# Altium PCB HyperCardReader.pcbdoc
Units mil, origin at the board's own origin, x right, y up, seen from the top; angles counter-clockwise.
Board outline 2181.35 x 1859.05 mil, 2 copper layers (Top Layer, Bottom Layer); 44 components, 43 nets, 186 pads, 101 vias.
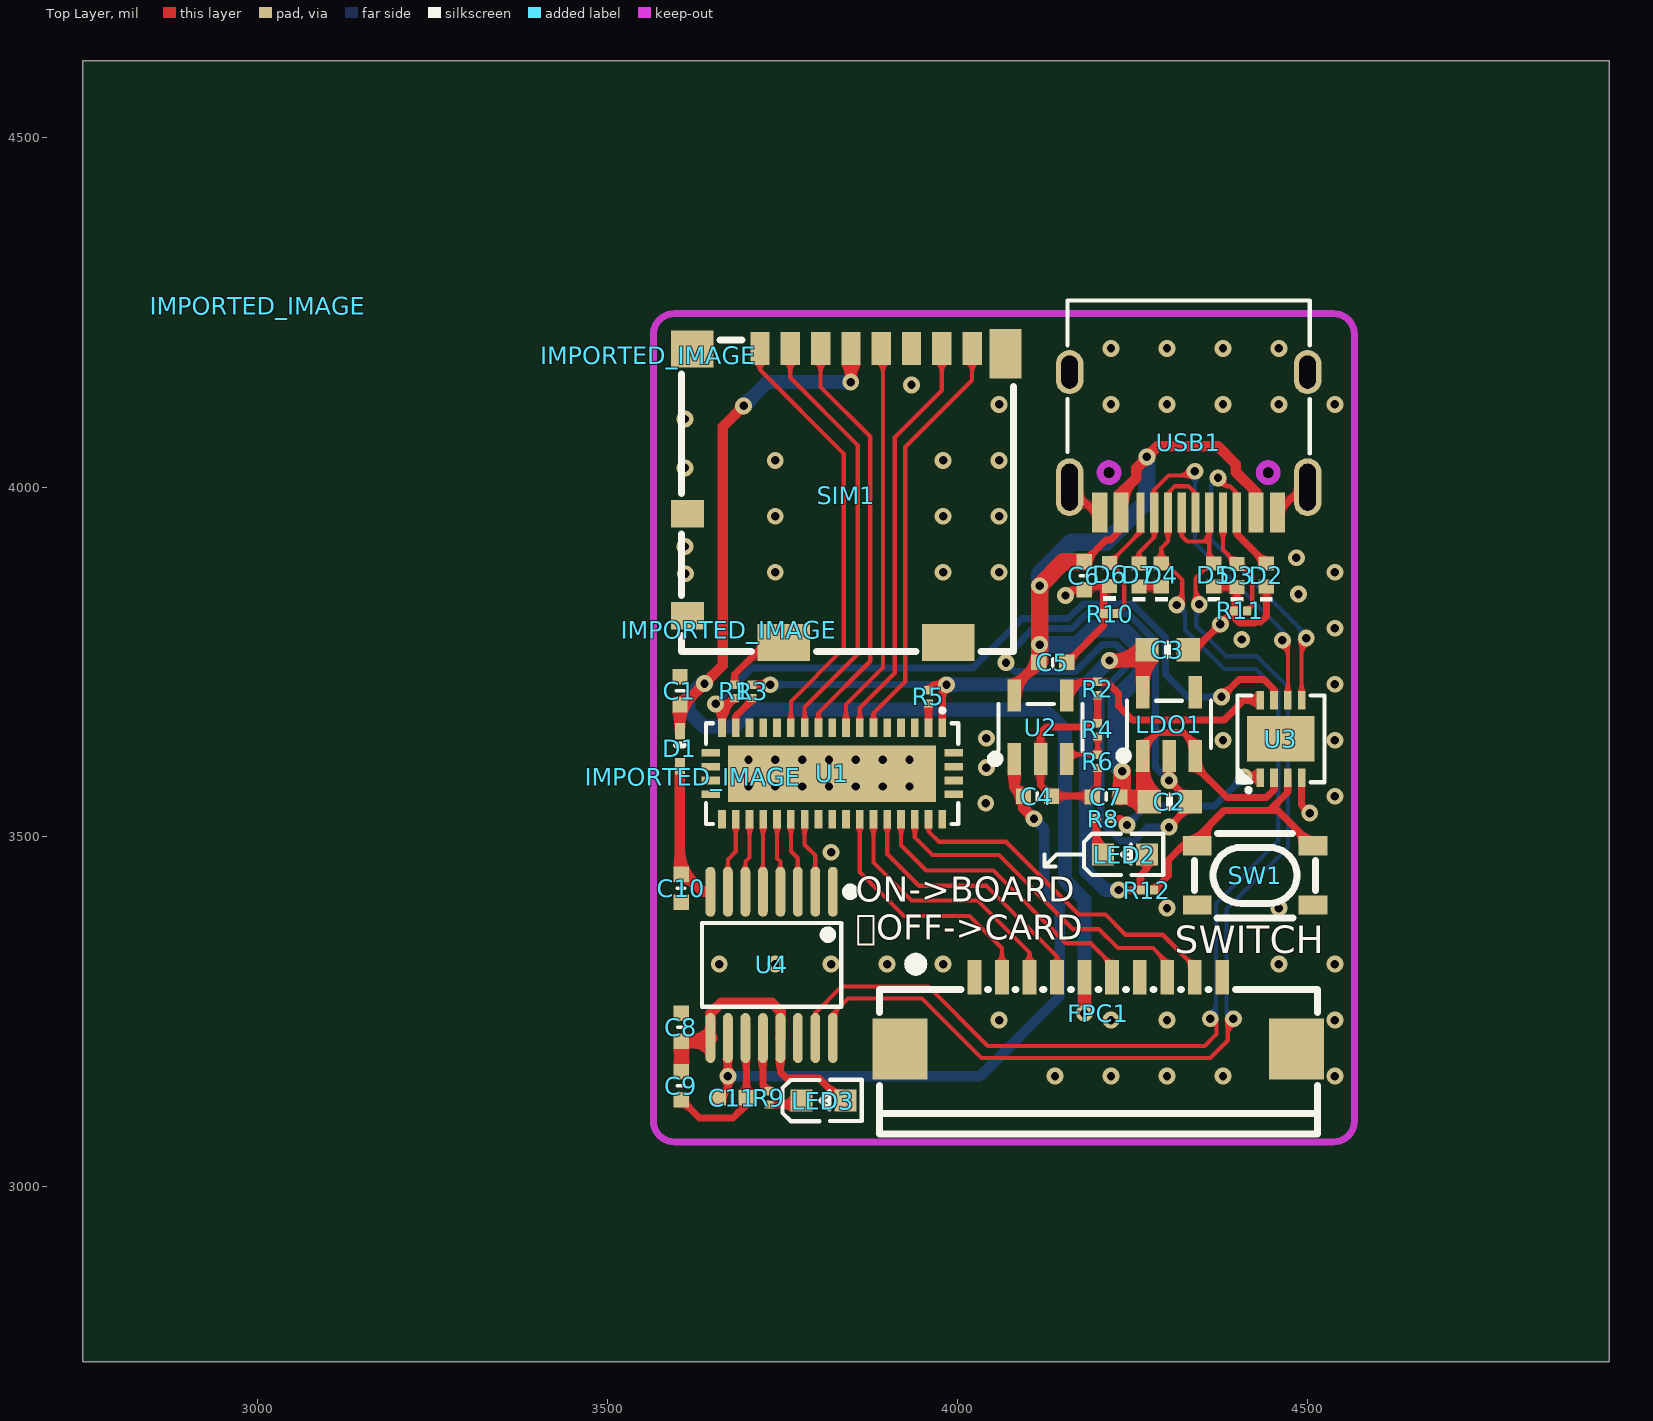
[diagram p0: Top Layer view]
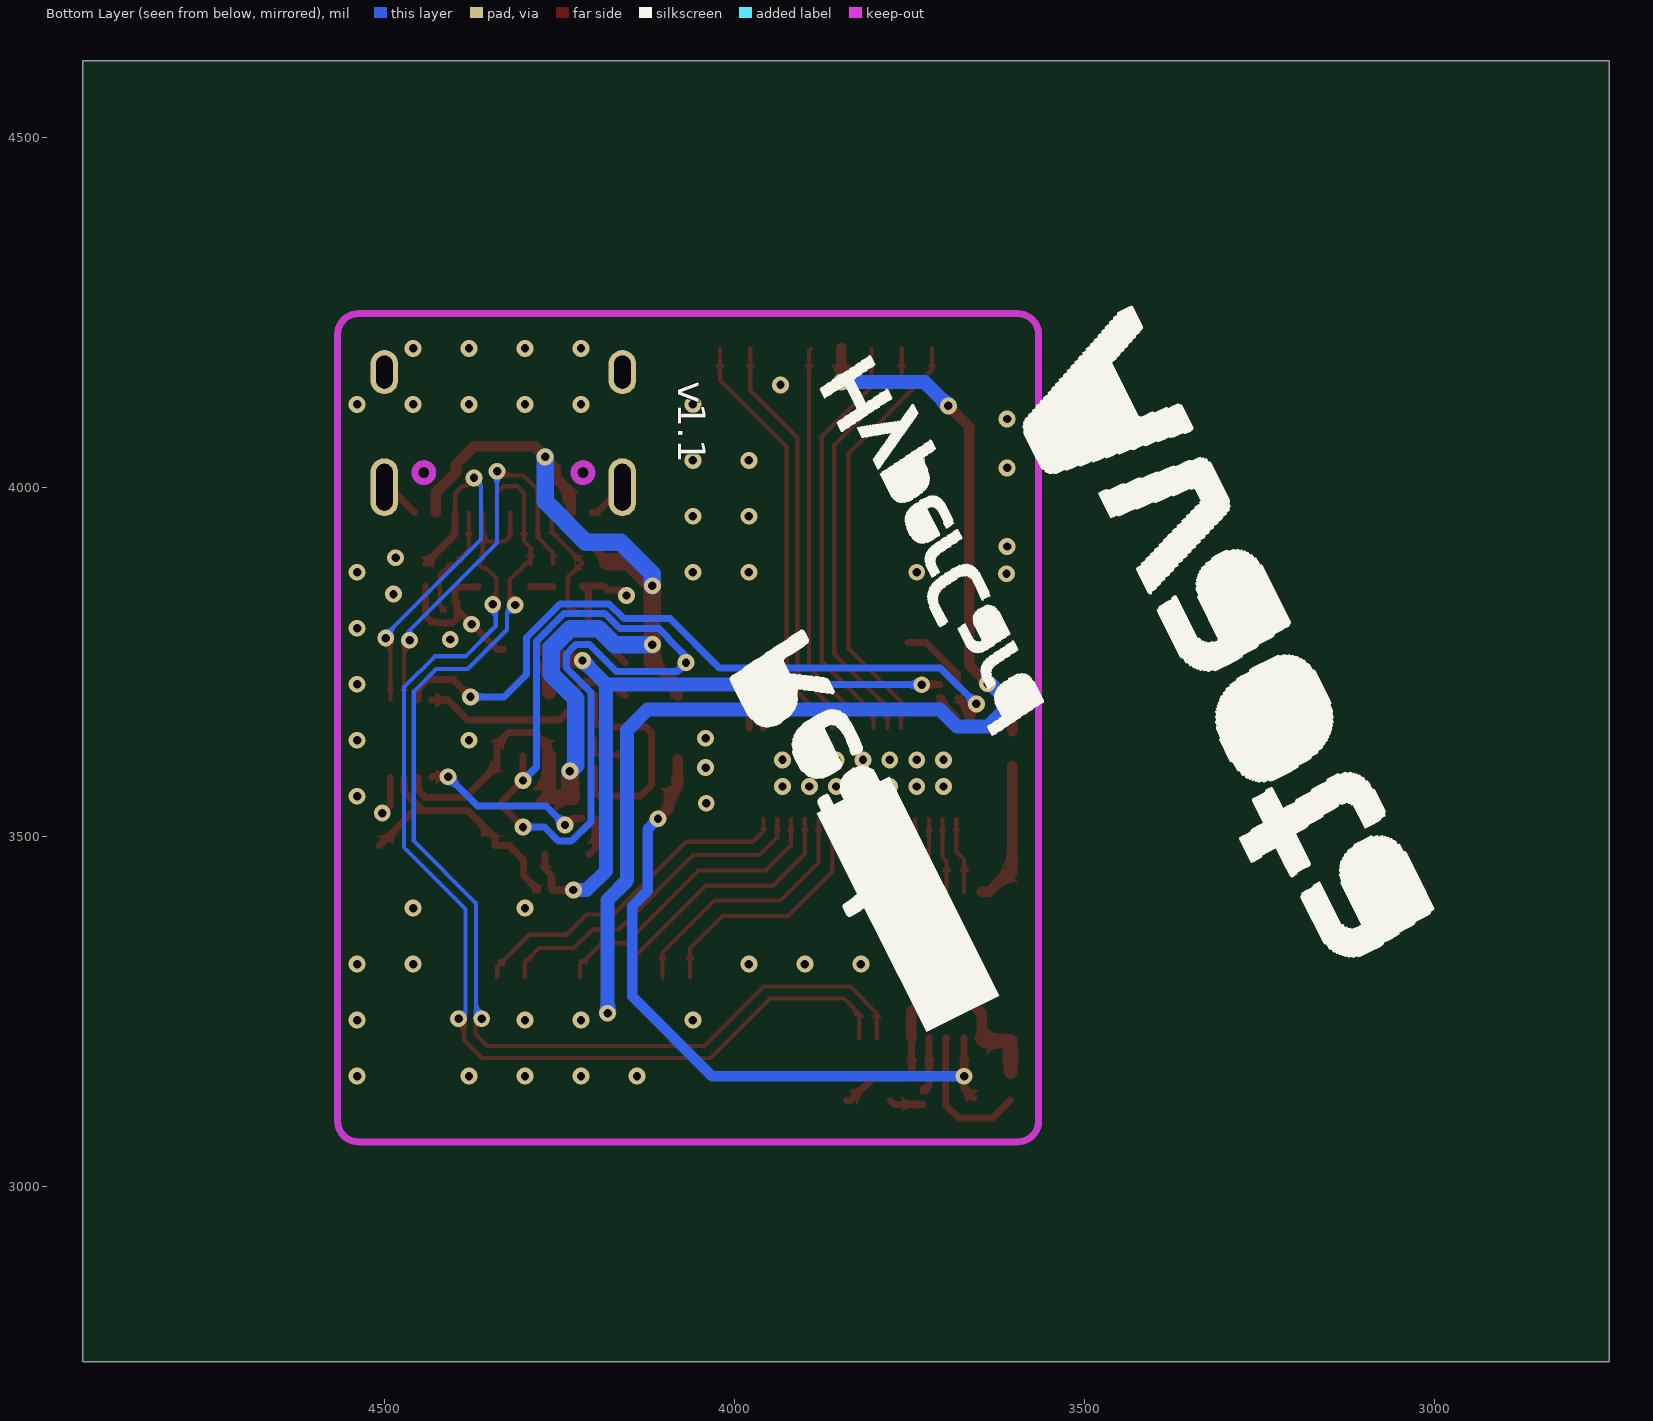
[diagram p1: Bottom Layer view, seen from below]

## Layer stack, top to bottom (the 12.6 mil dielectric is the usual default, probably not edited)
Top Layer: signal copper (thickness not stored)
Dielectric: dielectric 12.6, FR-4, Dk 4.8
Bottom Layer: signal copper (thickness not stored)

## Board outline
4931.35,2750 2750,2750 2750,4609.05 4931.35,4609.05

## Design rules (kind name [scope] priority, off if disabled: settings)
Clearance copperThickness1oz [All] p1: gap=7 ignorepadtopadclearanceinfootprint=FALSE except(4: Track-Track; 6: Track-SMDPad SMDPad-SMDPad Track-THPad SMDPad-THPad THPad-THPad Track-Via SMDPad-Via THPad-Via Via-Via Track-Fill SMDPad-Fill THPad-Fill Via-Fill Fill-Fill SMDPad-Region THPad-Region Via-Region Fill-Region Region-Region Track-Poly SMDPad-Poly THPad-Poly Via-Poly Fill-Poly Poly-Poly Track-Text SMDPad-Text THPad-Text Via-Text Fill-Text Region-Text Poly-Text Text-Text; 6.9: Track-Hole SMDPad-Hole THPad-Hole Via-Hole Fill-Hole Region-Hole Poly-Hole Text-Hole Sheet-Hole; 11.8: Track-Region Region-Poly Track-Sheet SMDPad-Sheet THPad-Sheet Via-Sheet Fill-Sheet Region-Sheet Poly-Sheet Text-Sheet)
Clearance copperThickness2oz [All] p1: gap=7 ignorepadtopadclearanceinfootprint=FALSE except(6: Track-SMDPad SMDPad-SMDPad Track-THPad SMDPad-THPad THPad-THPad Track-Via SMDPad-Via THPad-Via Via-Via Track-Fill SMDPad-Fill THPad-Fill Via-Fill Fill-Fill SMDPad-Region THPad-Region Via-Region Fill-Region Region-Region Track-Poly SMDPad-Poly THPad-Poly Via-Poly Fill-Poly Poly-Poly Track-Text SMDPad-Text THPad-Text Via-Text Fill-Text Region-Text Poly-Text Text-Text; 6.9: Track-Hole SMDPad-Hole THPad-Hole Via-Hole Fill-Hole Region-Hole Poly-Hole Text-Hole Sheet-Hole; 8: Track-Track; 11.8: Track-Region Region-Poly Track-Sheet SMDPad-Sheet THPad-Sheet Via-Sheet Fill-Sheet Region-Sheet Poly-Sheet Text-Sheet)
DiffPairsRouting differentialPair [All] p1: maxuncoupledlength=10 minlimit=0 maxlimit=5.9843 mostfreqgap=5.9843 toplayer_minwidth=5 toplayer_prefwidth=10 toplayer_maxwidth=100 bottomlayer_minwidth=5 bottomlayer_prefwidth=10 bottomlayer_maxwidth=100
PasteMaskExpansion pasteMaskExpansion [All] p1: expansion=0
PlaneConnect innerPlane [All] p1: planeconnectstyle=Relief reliefexpansion=20 reliefentries=4 reliefconductorwidth=10 reliefairgap=10
PolygonConnect copperRegion [All] p1: connectstyle=Relief reliefentries=4 reliefconductorwidth=10 polygonreliefangle="90 Angle" airgapwidth=10
RoutingVias viaSize [All] p1: viastyle="Through Hole" holewidth=12.0078 minholewidth=11.811 maxholewidth=248.0314 width=24.0158 minwidth=19.685 maxwidth=393.7008
SolderMaskExpansion solderMaskExpansion [All] p1: useseparateexpansions=TRUE expansion=2.0079 expansionbottom=2.0079
Width copperThickness1oz [All] p1: maxlimit=100 minlimit=5 preferedwidth=10
Width copperThickness2oz [All] p1: maxlimit=100 minlimit=8 preferedwidth=10

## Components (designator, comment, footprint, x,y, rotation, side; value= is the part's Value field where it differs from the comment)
C1 "CAP_0402" c0402-nsk 3603.35,3709 r270 top
C2 "CAP_0603" C0603-NSK 4303.35,3550 r180 top
C3 "CAP_0603" C0603-NSK 4300.35,3767.54 r180 top
C4 "CAP_0402" c0402-nsk 4114.36,3558.28 r180 top
C5 "CAP_0402" c0402-nsk 4136.36,3749.28 r180 top
C6 "CAP_0402" c0402-nsk 4181.35,3873 r90 top
C7 "CAP_0402" c0402-nsk 4212.35,3557 r0 top
C8 "CAP_0402" c0402-nsk 3605.35,3228 r270 top
C9 "CAP_0402" c0402-nsk 3605.35,3144 r90 top
C10 "CAP_0402" c0402-nsk 3605.25,3426.67 r90 top
C11 "CAP_0402" c0402-nsk 3678.35,3127 r180 top
D1 "B5819WT_C2997265" "SOD-523_L1.2-W0.8-LS1.6-RD-1 NSK" 3603.35,3626 r270 top
D2 "0402ESDA-05N" d0402 4441.35,3874 r90 top
D3 "0402ESDA-05N" d0402 4399.44,3873.72 r90 top
D4 "0402ESDA-05N" d0402 4291.35,3874 r90 top
D5 "0402ESDA-05N" d0402 4366.35,3874 r90 top
D6 "0402ESDA-05N" d0402 4217.35,3875 r90 top
D7 "0402ESDA-05N" d0402 4259.35,3874 r90 top
FPC1 "AFA01-S10FCC-00" FPC-SMD_AFA01-S10FCC-00 4201.35,3248 r0 top
IMPORTED_IMAGE "IMPORTED_IMAGE" IMPORTED_IMAGE 3000,4258.92 r0 top
IMPORTED_IMAGE "IMPORTED_IMAGE" IMPORTED_IMAGE 3557.69,4188.12 r0 top
IMPORTED_IMAGE "IMPORTED_IMAGE" IMPORTED_IMAGE 3621.76,3586.01 r0 top
IMPORTED_IMAGE "IMPORTED_IMAGE" IMPORTED_IMAGE 3672.82,3796.23 r0 top
LDO1 "ME6211C33M5G-N" SOT-23-5_L3.0-W1.7-P0.95-LS2.8-BL 4302.35,3661 r0 top
LED2 "LED_0603-R" LED_0603 4241.35,3475 r0 top
LED3 "LED_0603-R" LED_0603 3810.47,3123.31 r0 top
R1 "Res_0201" "r0201 nsk" 3681.35,3708 r90 top
R2 "Res_0201" "r0201 nsk" 4200.35,3712 r90 top
R3 "Res_0201" "r0201 nsk" 3706.35,3708 r90 top
R4 "Res_0201" "r0201 nsk" 4200.35,3653 r90 top
R5 "Res_0201" "r0201 nsk" 3958.35,3700 r90 top
R6 "Res_0201" "r0201 nsk" 4200.35,3608 r90 top
R8 "Res_0201" "r0201 nsk" 4208.35,3526 r0 top
R9 "Res_0201" "r0201 nsk" 3730.35,3127 r90 top
R10 "Res_0201" "r0201 nsk" 4218.35,3819 r0 top
R11 "Res_0201" "r0201 nsk" 4404.35,3823 r0 top
R12 "Res_0201" "r0201 nsk" 4271.35,3424 r0 top
SIM1 "1040310811" SIM-SMD_8P-1040310811 3841.35,3988 r180 top
SW1 "SKRPACE010" KEY-SMD_4P-L4.2-W3.2-P2.20-LS4.6 4425.35,3445 r0 top
U1 "TS3DV642A0RUAR" WFQFN-42_L9.0-W3.5-P0.50-BL-EP 3821.04,3590.48 r180 top
U2 "SY6280AAC_C55136" SOT-23-5_L3.0-W1.7-P0.95-LS2.8-BL 4118.77,3656.53 r0 top
U3 "STC8G1K08-36I-DFN8" DFN-8_L3.0-W3.0-P0.50-BL-EP 4462.35,3640 r0 top
U4 "GL823K-HCY04" SSOP-16_L4.9-W3.9-P0.64-LS6.0-BL 3734.35,3317 r180 top
USB1 "TYPEC-304-BCP16" USB-C-SMD_TYPEC-304-BCP16-1 4330.35,4064 r180 top

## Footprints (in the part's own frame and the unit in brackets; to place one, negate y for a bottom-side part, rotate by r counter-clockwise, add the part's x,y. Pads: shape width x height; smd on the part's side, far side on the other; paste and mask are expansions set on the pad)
c0402-nsk [mil]
  rect 22x22 smd: 1(-19.99,0) 2(20.01,0)
  silkscreen extent 0,-5 0,6
C0603-NSK [mm]
  rect 0.85x0.85 smd: 1(-0.75,0) 2(0.75,0)
  silkscreen extent 0,-0.21 0,0.21
d0402 [mil]
  rect 19.89x21.68 smd: 1(-16.4,0) 2(16.4,0)
  silkscreen extent -37,-9 -31,9
DFN-8_L3.0-W3.0-P0.50-BL-EP [mm]
  rect 0.28x0.665 smd: 1(-0.75,-1.407) 2(-0.25,-1.407) 3(0.25,-1.407) 4(0.75,-1.407) 5(0.75,1.407) 6(0.25,1.407) 7(-0.25,1.407) 8(-0.75,1.407)
  rect 2.45x1.65 smd: 9(0,0)
  silkscreen extent -1.58,-1.93 1.58,1.58
FPC-SMD_AFA01-S10FCC-00 [mm]
  rect 0.5x1.25 smd: 1(-4.5,1.3) 2(-3.5,1.3) 3(-2.501,1.3) 4(-1.5,1.3) 5(-0.501,1.3) 6(0.499,1.3) 7(1.5,1.3) 8(2.499,1.3) 9(3.5,1.3) 10(4.499,1.3)
  rect 2x2.2 smd: 11(-7.2,-1.3) 12(7.2,-1.3)
  silkscreen extent -7.94,-4.39 7.95,0.86
IMPORTED_IMAGE [mil]
KEY-SMD_4P-L4.2-W3.2-P2.20-LS4.6 [mm]
  rect 1.05x0.7 smd: 1(-2.1,1.075) 2(2.1,1.075) 3(-2.1,-1.075) 4(2.1,-1.075)
  silkscreen extent -2.2,-1.55 2.2,1.52
LED_0603 [mil]
  rect 31.5x31.5 smd: 1(-33.5,-0.4) 2(29.5,-0.2)
  silkscreen extent -61,-30 53,30
"r0201 nsk" [mil]
  rect 11.93x12.76 smd: 1(-9.51,0) 2(9.51,0)
SIM-SMD_8P-1040310811 [mm]
  rect 0.7x1.2 smd: 1(3.138,-5.337) 2(2.037,-5.337) 3(0.938,-5.337) 4(-0.162,-5.337) 5(-1.263,-5.337) 6(-2.363,-5.337) 7(-3.462,-5.337) 8(-4.562,-5.337)
  rect 1.17x1.8 smd: 9(-5.773,-5.138)
  rect 1.55x1.35 smd: 10(5.598,-5.313)
  rect 1.2x1 smd: 11(5.773,0.663) 12(5.773,4.363)
  rect 1.9x1.35 smd: 13(2.273,5.337) 14(-3.697,5.337)
  silkscreen extent -6.07,-5.64 5.99,5.67
"SOD-523_L1.2-W0.8-LS1.6-RD-1 NSK" [mm]
  rect 0.6x0.36 smd: 1(-0.635,0) 2(0.635,0)
  silkscreen extent -0.13,-0.13 -0.13,0.13
SOT-23-5_L3.0-W1.7-P0.95-LS2.8-BL [mm]
  rect 0.49x1.157 smd: 1(-0.95,-1.154) 2(0,-1.154) 3(0.95,-1.154)
  rect 0.49x1.175 smd: 4(0.95,1.154) 5(-0.95,1.154)
  silkscreen extent -1.8,-1.29 1.53,0.85
SSOP-16_L4.9-W3.9-P0.64-LS6.0-BL [mil]
  oval 14x71.45 smd: 1(-87.5,-104.52) 2(-62.5,-104.52) 3(-37.5,-104.52) 4(-12.5,-104.52) 5(12.5,-104.52) 6(37.5,-104.52) 7(62.5,-104.52) 8(87.5,-104.52) 9(87.5,104.52) 10(62.5,104.52) 11(37.5,104.52) 12(12.5,104.52) 13(-12.5,104.52) 14(-37.5,104.52) 15(-62.5,104.52) 16(-87.5,104.52)
  silkscreen extent -118,-110 100,60
USB-C-SMD_TYPEC-304-BCP16-1 [mm]
  oval 1x2.1 hole 0.6 slot 1.7 at 90 deg: 12(-4.32,1.633) 13(4.32,1.633)
  oval 1x1.6 hole 0.6 slot 1.2 at 90 deg: 14(-4.32,-2.547) 15(4.32,-2.547)
  rect 0.55x1.45 smd: A1B12(-3.225,2.547) A4B9(-2.45,2.547) B1A12(3.225,2.547) B4A9(2.45,2.547)
  rect 0.3x1.45 smd: A5(-1.25,2.547) A6(-0.25,2.547) A7(0.25,2.547) A8(1.25,2.547) B5(1.75,2.547) B6(0.75,2.547) B7(-0.75,2.547) B8(-1.75,2.547)
  Multi-Layer board cut-out: -3.215,1.102 -3.169,0.943 -3.051,0.826 -2.89,0.784 -2.729,0.826 -2.611,0.943 -2.565,1.102 -2.565,1.102 -2.611,1.262 -2.729,1.379 -2.89,1.421 -3.051,1.379 -3.169,1.262 -3.215,1.102
  Multi-Layer board cut-out: 2.565,1.102 2.611,0.943 2.729,0.826 2.89,0.784 3.051,0.826 3.169,0.943 3.215,1.102 3.215,1.102 3.169,1.262 3.051,1.379 2.89,1.421 2.729,1.379 2.611,1.262 2.565,1.102
  Multi-Layer keep-out circle w0.254: c-2.89,1.102 r0.325
  Multi-Layer keep-out circle w0.254: c2.89,1.102 r0.325
  silkscreen extent -4.4,-5.15 4.4,0.41
WFQFN-42_L9.0-W3.5-P0.50-BL-EP [mm]
  rect 0.28x0.665 smd: 1(-3.998,-1.658) 2(-3.498,-1.658) 3(-2.998,-1.658) 4(-2.498,-1.658) 5(-1.998,-1.658) 6(-1.498,-1.658) 7(-0.998,-1.658) 8(-0.498,-1.658) 9(0.002,-1.658) 10(0.502,-1.658) 11(1.002,-1.658) 12(1.502,-1.658) 13(2.002,-1.658) 14(2.502,-1.658) 15(3.002,-1.658) 16(3.502,-1.658) 17(4.002,-1.658) 22(4.002,1.658) 23(3.502,1.658) 24(3.002,1.658) 25(2.502,1.658) 26(2.002,1.658) 27(1.502,1.658) 28(1.002,1.658) 29(0.502,1.658) 30(0.002,1.658) 31(-0.498,1.658) 32(-0.998,1.658) 33(-1.498,1.658) 34(-1.998,1.658) 35(-2.498,1.658) 36(-2.998,1.658) 37(-3.498,1.658) 38(-3.998,1.658)
  rect 0.665x0.28 smd: 18(4.41,-0.75) 19(4.41,-0.25) 20(4.41,0.25) 21(4.41,0.75) 39(-4.405,0.75) 40(-4.405,0.25) 41(-4.405,-0.25) 42(-4.405,-0.75)
  rect 7.55x2.05 smd: 43(0.002,0)
  silkscreen extent -4.57,-2.36 4.58,1.83

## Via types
v1: diameter 24.02, hole 12.01, Top Layer to Bottom Layer, 101 vias

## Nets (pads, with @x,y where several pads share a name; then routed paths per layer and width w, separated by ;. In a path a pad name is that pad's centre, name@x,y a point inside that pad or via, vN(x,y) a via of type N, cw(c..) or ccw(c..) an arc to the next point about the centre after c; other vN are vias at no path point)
$1N1961: R4.1 R6.2 U2.3 | length 72.8
  Top Layer w6: U2.3 4162.57,3617.51 R6.2 R4.1
$1N4375: LED3.1 R9.1 | length 48.9
  Top Layer w10: R9.1 3771.55,3117.49 LED3.1
$1N4433: LED2.1 R8.1 | length 55.1
  Top Layer w10: R8.1 4198.84,3483.61 LED2.1
CC1: D3.2 R11.2 USB1.A5 | length 164.9
  Top Layer w6: USB1.A5 4379.56,3910.01 4380.24,3909.33 4380.91,3909.33 4386.18,3904.07 4386.18,3903.39 D3.2 4405.23,3890.12 4421.35,3874 4421.35,3830.49 R11.2
CC2: D6.2 R10.2 USB1.B5 | length 176.4
  Top Layer w6: R10.2 4238.35,3829.49 4238.35,3871.09 4231.91,3877.53 4231.22,3877.53 D6.2 4261.45,3935.5 USB1.B5
CPUX-RX: D2.2 U3.5 USB1.B8 | length 534.9
  Top Layer w6: v1(4372.35,4013) 4384.12,4001.23 4389.19,4001.23 4399.25,3991.17 USB1.B8 ; U3.5 4491.88,3777.53 v1(4498.35,3784)
  Top Layer w10: USB1.B8 4399.25,3932.5 D2.2
  Bottom Layer w6: v1(4372.35,4013) 4372.35,4012 4362.35,4002 4362.35,3925 4498.35,3789 v1(4498.35,3784)
CPUX-TX: D7.2 U3.6 USB1.A8 | length 565.8
  Top Layer w6: D7.2 4259.35,3906 4281.14,3927.79 USB1.A8 4281.14,3995.79 4301.84,4016.49 4333.38,4016.49 v1(4339.38,4022.49) ; v1(4464.35,3781) 4472.19,3773.16 U3.6
  Bottom Layer w6: v1(4339.38,4022.49) 4339.35,3920.14 4464.35,3795.14 v1(4464.35,3781)
EN: R5.1 U1.2 | length 34.9
  Top Layer w10: R5.1 3958.74,3690.1 U1.2
GND: C1.1 C2.1 C3.1 C4.1 C5.1 C6.1 C7.1 C8.1 C9.1 C10.1 C11.1 D2.1 D3.1 D4.1 D5.1 D6.1 D7.1 FPC1.1 FPC1.7 FPC1.11 FPC1.12 LDO1.2 R1.2 R2.1 R4.2 R6.1 R10.1 R11.1 SIM1.6 SIM1.9 SIM1.10 SIM1.12 SIM1.13 SIM1.14 SW1.3 SW1.4 U1.43 U2.2 U3.4 U3.9 U4.1 U4.11 U4.14 USB1.12 USB1.13 USB1.14 USB1.15 USB1.A1B12 USB1.B1A12 | length 2477
  Top Layer w10: C9.1 3631.36,3098 3679.35,3098 3698.35,3116.99 C11.1 3698.35,3210.99 U4.11 ; R1.2 3681.35,3732 3727.22,3777.86 SIM1.13 ; v1(4154.35,3845.01) 4162.35,3853.01 C6.1 4186.95,3858.6 D6.1 4208.84,3850.09 R10.1 4208.84,3801.77 C5.1 ; USB1.13 4196.29,3963.7 USB1.B1A12 ; R6.1 4200.35,3564.99 C7.1 4191.07,3558.28 C4.1 4118.77,3573.87 U2.2 4118.77,3649.42 4126.35,3657 4185.98,3657 4189.42,3660.44 4198.28,3660.44 R4.2 R2.1 ; D7.1 D4.1 ; v1(4302.35,3514) 4332.88,3544.53 C2.1 v1(4302.35,3580.53) LDO1.2 ; C3.1 4339.38,3767.54 v1(4375.83,3803.99) R11.1 ; D5.1 4366.63,3857.32 D3.1 4399.44,3836.46 4396.91,3833.93 4396.91,3825.07 R11.1 ; D2.1 4441.35,3815 4433.35,3807 4425.74,3807 4424.38,3805.64 4403.34,3805.64 4396.91,3812.07 4396.91,3820.93 R11.1 ; USB1.A1B12 4493.34,3999.72 USB1.12 ; U3.4 4491.88,3545.47 v1(4503.35,3534)
  Bottom Layer w10: v1(4302.35,3514) 4271.87,3514 4251.87,3494.01 4232.83,3494.01 4205.28,3521.56 4205.28,3706.41 4240.34,3741.48 4240.34,3761.52 4226.87,3774.99 4207.34,3774.99 4168.88,3736.53 4081.82,3736.53 v1(4069.35,3749) 4069.35,3758 4094.36,3783.01 4094.36,3784.31 4107.83,3797.78 4163.71,3797.78 4184.95,3819.02 4243.7,3819.02 4283.37,3779.35 4283.37,3599.5 v1(4302.35,3580.53)
  other v1: 4139.45,3158.1 4219.45,3158.1 4299.45,3158.1 4379.45,3158.1 4539.45,3158.1 4059.45,3238.1 4219.45,3238.1 4299.45,3238.1 4539.45,3238.1 3659.45,3318.1 3739.45,3318.1 3819.45,3318.1 3899.45,3318.1 3979.45,3318.1 4459.45,3318.1 4539.45,3318.1 4299.45,3398.1 4459.45,3398.1 3819.45,3478.1 4040.35,3548 4539.45,3558.1 3701.31,3572 3739.66,3572 3778.01,3572 3816.35,3572 3854.7,3572 3893.04,3572 3931.39,3572 4041.35,3598.98 3701.35,3610 3739.7,3610 3778.04,3610 3816.39,3610 3854.73,3610 3893.08,3610 3931.42,3610 4379.45,3638.1 4539.45,3638.1 4041.35,3641 4539.45,3718.1 4406.35,3782 4539.45,3798.1 4487.35,3847 3611.35,3876 3739.45,3878.1 3979.45,3878.1 4059.45,3878.1 4539.45,3878.1 4484.35,3899 3610.35,3915 3739.45,3958.1 3979.45,3958.1 4059.45,3958.1 3610.35,4027.33 3739.45,4038.1 3979.45,4038.1 4059.45,4038.1 3610.35,4097.22 4059.45,4118.1 4219.45,4118.1 4299.45,4118.1 4379.45,4118.1 4459.45,4118.1 4539.45,4118.1 3934.35,4146 4219.45,4198.1 4299.45,4198.1 4379.45,4198.1 4459.45,4198.1
LED-READ: R9.2 U4.12 | length 79.5
  Top Layer w10: U4.12 3721.85,3145.01 R9.2
READ-VCC-EN: R2.2 U2.4 U3.8 | length 329.6
  Top Layer w10: U2.4 4175.73,3721.51 R2.2 4213.84,3721.51 4230.35,3705 4230.35,3687 4250.35,3667 4381.35,3667 4409.76,3695.41 U3.8
SDC-CARD-CLK: SIM1.5 U1.8 | length 565.2
  Top Layer w6: U1.8 3840.63,3689.28 3893.35,3742 3893.35,4195.84 SIM1.5
SDC-CARD-CMD: SIM1.3 U1.10 | length 602.5
  Top Layer w6: U1.10 3801.26,3676.91 3875.35,3751 3875.35,4072 3804.44,4142.91 SIM1.3
SDC-CARD-D0: SIM1.7 U1.7 | length 591
  Top Layer w6: U1.7 3860.31,3683.96 3910.35,3734 3910.35,4071 3977.67,4138.31 SIM1.7
SDC-CARD-D1: SIM1.8 U1.6 | length 600.8
  Top Layer w6: U1.6 3880,3676.65 3925.35,3722 3925.35,4057 4020.98,4152.62 SIM1.8
SDC-CARD-D2: SIM1.1 U1.12 | length 623.2
  Top Layer w6: SIM1.1 3717.83,4167.52 3837.35,4048 3837.35,3769 3761.89,3693.54 U1.12
SDC-CARD-D3: SIM1.2 U1.11 | length 613.6
  Top Layer w6: SIM1.2 3761.14,4156.22 3857.35,4060 3857.35,3761 3781.57,3685.22 U1.11
SDC-CARD-DET: SIM1.11
SDC-READ-CLK: U1.26 U4.4 | length 105.6
  Top Layer w6: U1.26 3742.2,3469.15 3746.85,3464.5 U4.4
SDC-READ-CMD: U1.25 U4.5 | length 104
  Top Layer w6: U4.5 3721.85,3524.56 U1.25
SDC-READ-D0: U1.27 U4.3 | length 107.8
  Top Layer w6: U1.27 3761.89,3479.46 3771.85,3469.5 U4.3
SDC-READ-D1: U1.28 U4.2 | length 110
  Top Layer w6: U1.28 3781.57,3488.78 3796.85,3473.5 U4.2
SDC-READ-D2: U1.23 U4.7 | length 108.4
  Top Layer w6: U4.7 3671.85,3467.5 3683.15,3478.8 U1.23
SDC-READ-D3: U1.24 U4.6 | length 106.2
  Top Layer w6: U4.6 3696.85,3464.5 3702.83,3470.48 U1.24
SDC-TF-CLK: FPC1.6 U1.35 | length 427.7
  Top Layer w6: U1.35 3919.37,3487.98 3955.35,3452 4051.35,3452 4155.35,3348 4190.35,3348 4221,3317.36 FPC1.6
SDC-TF-CMD: FPC1.4 U1.34 | length 382.8
  Top Layer w6: U1.34 3899.68,3475.67 3945.35,3430 4041.35,3430 4142.3,3329.05 FPC1.4
SDC-TF-D0: FPC1.8 U1.36 | length 482.1
  Top Layer w6: U1.36 3939.05,3499.3 3964.35,3474 4059.35,3474 4165.35,3368 4202.35,3368 4229.35,3341 4279.35,3341 4299.75,3320.61 FPC1.8
SDC-TF-D1: FPC1.9 U1.37 | length 493.2
  Top Layer w6: U1.37 3958.74,3507.61 3973.35,3493 4069.35,3493 4173.35,3389 4211.35,3389 4240.35,3360 4293.35,3360 4339.15,3314.2 FPC1.9
SDC-TF-D2: FPC1.2 U1.32 | length 365.3
  Top Layer w6: U1.32 3860.31,3450.04 3923.35,3387 4017.35,3387 4063.55,3340.8 FPC1.2
SDC-TF-D3: FPC1.3 U1.33 | length 373.4
  Top Layer w6: U1.33 3880,3463.35 3934.35,3409 4028.35,3409 4102.9,3334.45 FPC1.3
SDC-TF-DET: FPC1.10
SEL: R1.1 U1.17 U3.7 | length 1038.7
  Top Layer w10: v1(3654.35,3690) 3654.35,3689.71 3663.46,3680.6 ; U1.17 3663.46,3680.6 ; R1.1 3663.46,3680.6 ; v1(4377.35,3700) 4402.35,3725 4438.35,3725 4452.51,3710.84 U3.7
  Bottom Layer w10: v1(3654.35,3690) 3705.35,3741 4021.35,3741 4092.15,3811.8 4157.9,3811.8 4179.14,3833.04 4249.5,3833.04 4297.39,3785.15 4297.39,3731.96 4329.35,3700 v1(4377.35,3700)
SEL1: R3.1 U1.16 | length 54
  Top Layer w10: U1.16 3683.15,3672.8 3691.89,3681.54 3692.28,3681.54 3698.71,3687.97 3698.71,3688.36 3707.35,3697 R3.1@3707.35,3699.49
SEL1-LED: R8.2 U3.1 | length 247.9
  Top Layer w10: R8.2 4233.35,3526 v1(4242.35,3517) ; v1(4409.35,3586) 4431.41,3586 U3.1
  Bottom Layer w10: v1(4242.35,3517) 4269.35,3544 4367.35,3544 v1(4409.35,3586)
SEL-BTN: R12.2 SW1.1 SW1.2 U3.3 | length 372.9
  Top Layer w10: R12.2 4301.35,3444.49 4301.35,3467 4321.67,3487.32 SW1.1 4342.67,3499.32 4381.35,3538 4446.35,3538 ; U3.3 4472.19,3563.84 4446.35,3538 ; SW1.2 4457.35,3538 4446.35,3538
USB0-DM: D5.2 U4.16 USB1.A7 USB1.B7 | length 1632.7
  Top Layer w6: U4.16 3821.85,3247.5 3843.35,3269 3949.35,3269 4034.35,3184 4361.35,3184 4386.35,3209 4386.35,3232 v1(4394.35,3240) ; USB1.A7 4320.51,3929.84 4328.35,3922 4352.22,3922 4359.88,3929.66 ; v1(4345.53,3832.18) 4340.35,3837.37 4340.35,3869.62 4355.13,3884.4 4360.35,3884.4 D5.2 4359.88,3896.87 4359.88,3929.66 ; USB1.B7 4359.88,3929.66
  Bottom Layer w6: v1(4345.53,3832.18) 4341.35,3828 4341.35,3801 4384.35,3758 4428.35,3758 4472.35,3714 4472.35,3485 4384.35,3397 4384.35,3250 v1(4394.35,3240)
USB0-DP: D4.2 U4.15 USB1.A6 USB1.B6 | length 1672.6
  Top Layer w6: U4.15 3796.85,3248.5 3834.35,3286 3958.35,3286 4043.35,3201 4353.35,3201 4370.35,3218 4370.35,3231 v1(4361.35,3240) ; v1(4313.36,3831.38) 4321.35,3839.37 4321.35,3867 4294.65,3893.7 D4.2 4291.35,3913 4300.82,3922.47 USB1.B6 4300.82,3991.17 4310.88,4001.23 4330.14,4001.23 4340.19,3991.18 USB1.A6
  Bottom Layer w6: v1(4313.36,3831.38) 4313.97,3831.38 4325.35,3820 4325.35,3796 4381.35,3740 4426.35,3740 4458.35,3708 4458.35,3494 4369.35,3405 4369.35,3248 v1(4361.35,3240)
VBUS-USB: C2.2 C5.2 C6.2 C7.2 LDO1.1 LDO1.3 U2.5 U3.2 USB1.A4B9 USB1.B4A9 | length 1731.8
  Top Layer w10: C6.2 4212.52,3924.18 4218.76,3924.18 4233.89,3939.31 USB1.B4A9 ; LDO1.1 4264.95,3628.6 4285.69,3649.34 4323.01,3649.34 4339.75,3632.6 LDO1.3 4339.75,3601.6 4385.35,3556 4441.35,3556 4452.51,3567.16 U3.2
  Top Layer w15: U2.5 4081.37,3714.3 C5.2 ; USB1.B4A9 4233.89,3991.54 4255.86,4013.51 4255.86,4026.56 4270.71,4041.41 v1(4270.71,4043) 4285.71,4058 4372.35,4058 4397.84,4032.51 4397.84,4021.48 4426.81,3992.51 USB1.A4B9
  Top Layer w20: C7.2 C2.2@4266.82,3557 ; LDO1.1 4264.95,3558.87 C2.2@4266.82,3557 ; C2.2 C2.2@4266.82,3557
  Top Layer w25: C5.2 4117.36,3750.28 v1(4117.36,3774.79) v1(4117.36,3859.01) 4151.36,3893.01 C6.2 ; C7.2 4235.35,3559.99 v1(4235.35,3594)
  Bottom Layer w25: v1(4117.36,3774.79) 4171.14,3774.79 4193.86,3797.51 4234.79,3797.51 4261.86,3770.44 4261.86,3732.56 4226.79,3697.5 4226.79,3602.56 v1(4235.35,3594) ; v1(4117.36,3859.01) 4117.36,3876.01 4162.35,3921 4212.35,3921 4270.71,3979.36 v1(4270.71,4043)
VCC-3V3-CARD: C10.2 D1.2 U4.8 | length 212.1
  Top Layer w15: D1.2 C10.2@3603.35,3454 ; C10.2 3603.35,3448.58 C10.2@3603.35,3454 ; U4.8 3635.83,3421.52 C10.2@3603.35,3454
VCC-3V3-LDO: C3.2 LDO1.5 LED2.2 R3.2 R5.2 R12.1 U1.1 | length 1144.9
  Top Layer w10: R3.2 v1(3732.35,3717.51) ; R5.2 3966.35,3717.51 v1(3984.35,3717.51) 3978.42,3711.58 U1.1 ; v1(4230.35,3424) R12.1 4261.35,3424.49 4261.35,3445 4270.85,3454.5 LED2.2
  Top Layer w20: v1(4217.35,3752) 4255.29,3752 C3.2@4264.95,3761.66 ; LDO1.5 C3.2@4264.95,3761.66 ; C3.2 C3.2@4264.95,3761.66
  Bottom Layer w10: v1(3732.35,3717.51) v1(3984.35,3717.51)
  Bottom Layer w20: v1(3984.35,3717.51) 4183.86,3717.51 ; v1(4217.35,3752) 4183.86,3718.51 4183.86,3717.51 ; v1(4230.35,3424) 4211.35,3424 4183.86,3451.49 4183.86,3717.51
VCC-CARD: C1.2 D1.1 FPC1.5 SIM1.4 | length 1808.9
  Top Layer w15: D1.1 C1.2 3608.35,3688.99 v1(3638.38,3719.02) 3664.35,3745 3664.35,4086 v1(3694.35,4116) ; v1(3847.35,4150) 3847.75,4150.4 SIM1.4
  Top Layer w18: v1(4181.35,3248) 4181.65,3248.3 FPC1.5
  Bottom Layer w20: v1(3638.38,3719.02) 3634.38,3719.02 3615.35,3700 3615.35,3680 3637.35,3658 3682.35,3658 3706.35,3682 4124.35,3682 4153.35,3653 4153.35,3438 4181.35,3410 v1(4181.35,3248) ; v1(3694.35,4116) 3728.35,4150 v1(3847.35,4150)
VCC-READ: C4.2 C11.2 U2.1 U4.10 | length 978.9
  Top Layer w10: C11.2 3671.85,3140.51 v1(3671.85,3157.8) U4.10
  Top Layer w15: U2.1 4081.37,3571.27 C4.2 4094.36,3540.99 v1(4109.35,3526)
  Bottom Layer w15: v1(3671.85,3157.8) 4032.15,3157.8 4146.35,3272 4146.35,3401 4124.35,3423 4124.35,3511 v1(4109.35,3526)
VDD-3V3: C8.2 C9.2 LED3.2 U4.9 U4.13 | length 431.2
  Top Layer w10: U4.13 3746.85,3163.5 3755.35,3155 3802.35,3155 3834.24,3123.11 LED3.2
  Top Layer w15: U4.9 3646.85,3247.5 3662.35,3263 3734.35,3263 3747.35,3250 3747.35,3212.98 U4.13
  Top Layer w20: C9.2 C8.2 3642.37,3207.99 U4.9
pads on no net: LDO1.4 U1.3 U1.4 U1.5 U1.9 U1.13 U1.14 U1.15 U1.18 U1.19 U1.20 U1.21 U1.22 U1.29 U1.30 U1.31 U1.38 U1.39 U1.40 U1.41 U1.42

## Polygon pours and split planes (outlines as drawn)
GND on Top Layer (solid, remove dead copper, pour order 0): 3474.35,3000 4681.35,3000 4681.35,4338 3474.35,4338
GND on Bottom Layer (solid, remove dead copper, pour order 2): 3455.18,3021.05 4662.18,3021.05 4662.18,4359.05 3455.18,4359.05

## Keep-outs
Board Outline Layer:
  lines w10: 3565.35,3094 ccw(c3595.35,3094) 3595.35,3064 4537.35,3064 ccw(c4537.35,3094) 4567.35,3094 4567.35,4218 ccw(c4537.35,4218) 4537.35,4248 3595.35,4248 ccw(c3595.35,4218) 3565.35,4218 3565.35,3094

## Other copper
Top Layer:
  region net VCC-CARD: 3616.69,3707.95 3627.06,3697.1 ccw(c3668.22,3655.94) 3614.35,3677.99 3592.83,3699.99 ccw(c3592.83,3739.77)
  region net VCC-CARD: 3610.85,3655.49 3595.85,3655.49 ccw(c3521.78,3655.49) 3592.35,3677.99 3614.35,3677.99 ccw(c3684.92,3655.49)
  region net VBUS-USB: 4232.36,3547 4232.36,3567 ccw(c4257.09,4710.45) 4257.09,3566.73 4257.09,3533.27 ccw(c4232.36,3517.86)
  region net VBUS-USB: 4254.95,3596.73 4274.95,3596.73 ccw(c4312.45,3596.73) 4289.95,3566.73 4257.09,3566.73 ccw(c4045.69,3566.73)
  region net VCC-3V3-LDO: 4274.95,3720.8 4254.95,3720.8 ccw(c3730.97,3720.8) 4254.09,3750.8 4287.56,3750.8 ccw(c4316.95,3720.8)
  region net VCC-3V3-LDO: 4224.09,3742 4224.09,3762 ccw(c4224.09,3799.5) 4254.09,3777 4254.09,3750.8 ccw(c4254.09,3695.29)
  region net VCC-READ: 4101.86,3540.99 4086.86,3540.99 ccw(c4079.46,3540.99) 4083.36,3547.28 4105.36,3547.28 ccw(c4109.25,3540.99)
  region net VCC-READ: 4076.07,3565.96 4086.68,3576.57 ccw(c4105.36,3596.87) 4105.36,3569.28 4083.36,3547.28 ccw(c4055.77,3547.28)
  region net VBUS-USB: 4105.75,3728.07 4095.14,3738.68 ccw(c4070.08,3763.74) 4105.36,3760.28 4127.36,3738.28 ccw(c4130.81,3703)
  region net VBUS-USB: 4190.58,3909.31 4197.65,3902.24 ccw(c4218.87,3886.33) 4192.35,3886.33 4174.67,3904.01 ccw(c4174.67,3930.52)
  region net VBUS-USB: 4266.82,3567 4266.82,3547 ccw(c4266.82,3271.15) 4243.36,3546 4243.36,3568 ccw(c4266.82,3842.85)
  region net VBUS-USB: 4222.85,3594 4247.85,3594 ccw(c4320.8,3568) 4243.36,3568 4221.36,3568 ccw(c3996.02,3594)
  region net VDD-3V3: 3615.35,3166.99 3595.35,3166.99 ccw(c3144.85,3166.99) 3594.35,3196.99 3616.35,3196.99 ccw(c4065.85,3166.99)
  region net VDD-3V3: 3642.37,3217.99 3642.37,3197.99 ccw(c3642.37,2859.11) 3616.35,3196.99 3616.35,3218.99 ccw(c3642.37,3556.88)
  region net VDD-3V3: 3595.35,3205.01 3615.35,3205.01 ccw(c4065.85,3205.01) 3616.35,3175.01 3594.35,3175.01 ccw(c3144.85,3205.01)
  region net VCC-3V3-CARD: 3629.17,3438.78 3619.02,3427.72 ccw(c3595.15,3395.9) 3595.15,3435.68 3616.25,3457.68 ccw(c3673.05,3482.66)
  region net VCC-3V3-CARD: 3595.85,3480.18 3610.85,3480.18 ccw(c3660.43,3480.18) 3616.25,3457.68 3594.25,3457.68 ccw(c3436.85,3480.18)
  region net VCC-READ: 3667.58,3143.3 3674.65,3136.23 ccw(c3695.86,3120.32) 3669.35,3120.32 3651.67,3138 ccw(c3651.67,3164.52)
  region net CPUX-RX: 4425.2,3899.47 4433.17,3905.65 ccw(c4449.08,3926.86) 4449.08,3900.34 4430.51,3883.56 ccw(c4403.99,3883.56)
  region net CC1: 4385.42,3899.91 4390.56,3903.25 ccw(c4400.1,3915.98) 4400.1,3900.07 4388.6,3890.36 ccw(c4372.69,3890.36)
  region net CC1: 4415.02,3884.57 4416.97,3874.14 ccw(c4353.95,3811.12) 4410.28,3880.18 4410.28,3892.57 ccw(c4428.27,3897.82)
  region net USB0-DP: 4306.93,3885.66 4309.29,3874.82 ccw(c4281.17,3846.7) 4302.19,3880.46 4302.19,3893.66 ccw(c4320.18,3898.91)
  region net USB0-DP: 4288.35,3909.34 4294.35,3909.34 ccw(c4305.6,3909.34) 4298.85,3900.34 4283.85,3900.34 ccw(c4277.1,3909.34)
  region net USB0-DM: 4356.88,3909.34 4362.88,3909.34 ccw(c4374.13,3909.34) 4367.38,3900.34 4355.51,3900.34 ccw(c4326.69,3909.34)
  region net CC2: 4231.37,3881.62 4226.23,3878.27 ccw(c4216.69,3865.55) 4216.69,3881.46 4228.19,3891.16 ccw(c4244.1,3891.16)
  region net CC2: 4226.23,3904.53 4231.37,3901.18 ccw(c4244.1,3891.64) 4228.19,3891.64 4216.69,3901.34 ccw(c4216.69,3917.25)
  region net CPUX-TX: 4256.35,3906 4262.35,3906 ccw(c4268.15,3906) 4266.85,3900.34 4251.85,3900.34 ccw(c4250.55,3906)
  region net SDC-TF-D2: 4060.55,3332.79 4066.55,3332.79 ccw(c4077.8,3332.79) 4071.05,3323.79 4056.05,3323.79 ccw(c4049.3,3332.79)
  region net SDC-TF-D3: 4099.9,3332.79 4105.9,3332.79 ccw(c4117.15,3332.79) 4110.4,3323.79 4095.4,3323.79 ccw(c4088.65,3332.79)
  region net SDC-TF-CMD: 4139.3,3329.05 4145.3,3329.05 ccw(c4150.62,3329.05) 4149.8,3323.79 4134.8,3323.79 ccw(c4133.97,3329.05)
  region net VCC-CARD: 4190.65,3248.3 4172.65,3248.3 ccw(c3762.18,3248.29) 4171.8,3274.58 4191.49,3274.58 ccw(c4601.11,3248.29)
  region net SDC-TF-CLK: 4207.97,3326.14 4215.62,3326.98 ccw(c4225.16,3339.7) 4225.16,3323.79 4211.15,3316.59 ccw(c4195.24,3316.59)
  region net SDC-TF-D0: 4284.74,3331.36 4296.06,3328.53 ccw(c4309.31,3341.78) 4304.06,3323.79 4289.9,3323.79 ccw(c4267.35,3313.96)
  region net SDC-TF-D1: 4326.12,3322.99 4330.62,3326.98 ccw(c4340.16,3339.7) 4340.16,3323.79 4329.3,3313.44 ccw(c4313.39,3313.44)
  region net VBUS-USB: 4272.94,3643.66 4279.9,3636.48 ccw(c4301.11,3620.57) 4274.6,3620.57 4257.03,3638.36 ccw(c4257.03,3664.87)
  region net VBUS-USB: 4354.7,3593.72 4346.78,3587.5 ccw(c4330.87,3566.29) 4330.87,3592.8 4349.4,3609.63 ccw(c4375.91,3609.63)
  region net VBUS-USB: 4324.8,3640.48 4334.62,3644.8 ccw(c4350.21,3660.39) 4349.4,3638.36 4330.1,3624.57 ccw(c4303.59,3624.57)
  region net $1N4433: 4193.84,3505.35 4203.84,3505.35 ccw(c4222.59,3505.35) 4211.34,3490.35 4192.1,3490.35 ccw(c4128.32,3505.35)
  region net VCC-3V3-LDO: 4275.85,3454.5 4265.85,3454.5 ccw(c4258.35,3450.59) 4258.35,3459.05 4283.35,3459.05 ccw(c4283.35,3450.59)
  region net $1N4375: 3746.22,3112.49 3746.22,3122.49 ccw(c3746.22,3141.24) 3761.22,3129.99 3761.22,3107.16 ccw(c3746.22,3088.72)
  region net VDD-3V3: 3818.92,3131.36 3820.26,3144.16 ccw(c3836.17,3165.38) 3836.17,3138.86 3824.22,3115.45 ccw(c3797.7,3115.45)
  region net SEL: 3674.48,3684.55 3667,3691.21 ccw(c3644.35,3713.86) 3674.97,3704.46 3687.73,3692.52 ccw(c3697.13,3661.9)
  region net READ-VCC-EN: 4213.84,3726.51 4213.84,3716.51 ccw(c4213.84,3689.87) 4206.73,3715.54 4206.73,3727.48 ccw(c4213.84,3753.15)
  region net READ-VCC-EN: 4178.97,3716.51 4178.97,3726.51 ccw(c4178.97,3843.33) 4193.97,3727.48 4193.97,3715.54 ccw(c4178.97,3599.69)
  region net VCC-3V3-LDO: 3727.73,3722.51 3727.73,3712.51 ccw(c3727.73,3595.69) 3712.73,3711.54 3712.73,3723.48 ccw(c3727.73,3839.33)
  region net SEL1: 3702.25,3684.83 3695.18,3691.9 ccw(c3681.13,3704.46) 3699.97,3704.46 3712.73,3692.52 ccw(c3732.61,3654.46)
  region net $1N1961: 4203.35,3628.52 4197.35,3628.52 ccw(c4183.67,3628.52) 4193.97,3637.52 4206.73,3637.52 ccw(c4217.03,3628.52)
  region net VCC-3V3-LDO: 3962.81,3721.05 3969.89,3713.97 ccw(c3982.72,3701.14) 3964.73,3703.54 3951.97,3715.48 ccw(c3948.73,3735.13)
  region net EN: 3963.74,3669.52 3953.74,3669.52 ccw(c3889.05,3669.52) 3951.97,3684.52 3964.73,3684.52 ccw(c4077.55,3669.52)
  region net $1N1961: 4197.35,3632.48 4203.35,3632.48 ccw(c4217.03,3632.48) 4206.73,3623.48 4193.97,3623.48 ccw(c4183.67,3632.48)
  region net $1N1961: 4184.97,3614.51 4184.97,3620.51 ccw(c4184.97,3635.64) 4193.97,3623.48 4193.97,3611.54 ccw(c4184.97,3599.38)
  region net SEL1-LED: 4233.35,3531 4233.35,3521 ccw(c4233.35,3487.41) 4223.83,3519.62 4223.83,3532.38 ccw(c4233.35,3564.59)
  region net $1N4433: 4203.84,3504.62 4193.84,3504.62 ccw(c4077.02,3504.62) 4192.87,3519.62 4204.81,3519.62 ccw(c4320.66,3504.62)
  region net LED-READ: 3718.31,3141.47 3725.39,3148.55 ccw(c3741.07,3164.23) 3736.73,3142.48 3723.97,3130.54 ccw(c3703.95,3127.11)
  region net $1N4375: 3751.73,3122.49 3751.73,3112.49 ccw(c3751.73,2995.67) 3736.73,3111.52 3736.73,3123.46 ccw(c3751.73,3239.31)
  region net CC2: 4233.18,3828.56 4237.01,3823.91 ccw(c4249.74,3814.36) 4233.83,3814.36 4223.63,3825.38 ccw(c4223.63,3841.29)
  region net CC1: 4419.18,3832.56 4423.01,3827.91 ccw(c4435.74,3818.36) 4419.83,3818.36 4409.63,3829.38 ccw(c4409.63,3845.29)
  region net SEL-BTN: 4288.14,3438.35 4294.8,3430.87 ccw(c4317.45,3408.22) 4286.83,3417.62 4274.89,3430.38 ccw(c4265.49,3461)
  region net VCC-3V3-LDO: 4240.87,3419 4240.87,3429 ccw(c4240.87,3511.33) 4255.87,3430.38 4255.87,3417.62 ccw(c4240.87,3336.67)
  region net VCC-3V3-LDO: 4256.35,3445 4266.35,3445 ccw(c4340.45,3445) 4267.81,3430.38 4255.87,3430.38 ccw(c4032,3445)
  region net SDC-CARD-D1: 4023.98,4165.51 4017.98,4165.51 ccw(c4006.73,4165.51) 4013.48,4174.51 4028.48,4174.51 ccw(c4035.23,4165.51)
  region net SDC-CARD-D0: 3980.67,4165.51 3974.67,4165.51 ccw(c3963.42,4165.51) 3970.17,4174.51 3985.17,4174.51 ccw(c3991.92,4165.51)
  region net SDC-CARD-CLK: 3896.35,4165.51 3890.35,4165.51 ccw(c3879.1,4165.51) 3885.85,4174.51 3900.85,4174.51 ccw(c3907.6,4165.51)
  region net VCC-CARD: 3855.25,4152.01 3840.25,4152.01 ccw(c3796.8,4152.01) 3833.97,4174.51 3861.52,4174.51 ccw(c3898.69,4152.01)
  region net SDC-CARD-CMD: 3807.44,4165.51 3801.44,4165.51 ccw(c3790.19,4165.51) 3796.94,4174.51 3811.94,4174.51 ccw(c3818.69,4165.51)
  region net SDC-CARD-D3: 3764.14,4165.51 3758.14,4165.51 ccw(c3746.89,4165.51) 3753.64,4174.51 3768.64,4174.51 ccw(c3775.39,4165.51)
  region net SDC-CARD-D2: 3720.83,4167.52 3714.83,4167.52 ccw(c3707.15,4167.52) 3710.33,4174.51 3725.33,4174.51 ccw(c3728.5,4167.52)
  region net SEL-BTN: 4321.67,3482.32 4321.67,3492.32 ccw(c4236.74,3499.82) 4322,3499.82 4322,3474.82 ccw(c4236.74,3474.82)
  region net SEL-BTN: 4342.68,3506.4 4367.43,3517.01 ccw(c4380.69,3503.75) 4362.13,3501.1 4326.77,3501.1 ccw(c4326.77,3527.62)
  region net SEL-BTN: 4482.06,3506.22 4496.02,3506.4 ccw(c4511.93,3527.62) 4511.93,3501.1 4487.36,3490.31 ccw(c4460.84,3490.31)
  region net VCC-3V3-LDO: 3973.42,3683.83 3983.42,3683.83 ccw(c4203.4,3683.83) 3983.93,3668.83 3972.91,3668.83 ccw(c3753.44,3683.83)
  region net EN: 3953.74,3683.83 3963.74,3683.83 ccw(c4183.72,3683.83) 3964.25,3668.83 3953.22,3668.83 ccw(c3733.75,3683.83)
  region net SDC-CARD-D1: 3877,3676.65 3883,3676.65 ccw(c3896.41,3676.65) 3885.51,3668.83 3874.48,3668.83 ccw(c3863.58,3676.65)
  region net SDC-CARD-D0: 3857.31,3677.83 3863.31,3677.83 ccw(c3880.69,3677.83) 3865.82,3668.83 3854.8,3668.83 ccw(c3839.93,3677.83)
  region net SDC-CARD-CLK: 3837.63,3677.83 3843.63,3677.83 ccw(c3861,3677.83) 3846.14,3668.83 3835.11,3668.83 ccw(c3820.25,3677.83)
  region net SDC-CARD-CMD: 3798.26,3676.91 3804.26,3676.91 ccw(c3818.5,3676.91) 3806.77,3668.83 3795.74,3668.83 ccw(c3784.01,3676.91)
  region net SDC-CARD-D3: 3778.57,3677.83 3784.57,3677.83 ccw(c3801.95,3677.83) 3787.08,3668.83 3776.06,3668.83 ccw(c3761.19,3677.83)
  region net SDC-CARD-D2: 3758.89,3677.83 3764.89,3677.83 ccw(c3782.26,3677.83) 3767.4,3668.83 3756.37,3668.83 ccw(c3741.51,3677.83)
  region net SEL1: 3678.15,3672.8 3688.15,3672.8 ccw(c3703.77,3672.8) 3688.66,3668.83 3677.63,3668.83 ccw(c3662.52,3672.8)
  region net SEL: 3658.46,3680.6 3668.46,3680.6 ccw(c3804.04,3680.6) 3668.97,3668.83 3657.95,3668.83 ccw(c3522.88,3680.6)
  region net SDC-READ-D2: 3686.15,3503.14 3680.15,3503.14 ccw(c3662.77,3503.14) 3677.63,3512.14 3688.66,3512.14 ccw(c3703.52,3503.14)
  region net SDC-READ-D3: 3705.83,3503.14 3699.83,3503.14 ccw(c3682.45,3503.14) 3697.32,3512.14 3708.34,3512.14 ccw(c3723.21,3503.14)
  region net SDC-READ-CMD: 3724.85,3503.14 3718.85,3503.14 ccw(c3696,3503.14) 3717,3512.14 3728.03,3512.14 ccw(c3739.19,3503.14)
  region net SDC-READ-CLK: 3745.2,3503.14 3739.2,3503.14 ccw(c3721.82,3503.14) 3736.69,3512.14 3747.71,3512.14 ccw(c3762.58,3503.14)
  region net SDC-READ-D0: 3764.89,3503.14 3758.89,3503.14 ccw(c3741.51,3503.14) 3756.37,3512.14 3767.4,3512.14 ccw(c3782.26,3503.14)
  region net SDC-READ-D1: 3784.57,3503.14 3778.57,3503.14 ccw(c3761.19,3503.14) 3776.06,3512.14 3787.08,3512.14 ccw(c3801.95,3503.14)
  region net SDC-TF-D2: 3863.31,3503.14 3857.31,3503.14 ccw(c3839.93,3503.14) 3854.8,3512.14 3865.82,3512.14 ccw(c3880.69,3503.14)
  region net SDC-TF-D3: 3883,3503.14 3877,3503.14 ccw(c3859.62,3503.14) 3874.48,3512.14 3885.51,3512.14 ccw(c3900.37,3503.14)
  region net SDC-TF-CMD: 3902.68,3503.14 3896.68,3503.14 ccw(c3879.3,3503.14) 3894.17,3512.14 3905.19,3512.14 ccw(c3920.06,3503.14)
  region net SDC-TF-CLK: 3922.37,3503.14 3916.37,3503.14 ccw(c3898.99,3503.14) 3913.85,3512.14 3924.88,3512.14 ccw(c3939.74,3503.14)
  region net SDC-TF-D0: 3942.05,3503.14 3936.05,3503.14 ccw(c3918.67,3503.14) 3933.54,3512.14 3944.56,3512.14 ccw(c3959.43,3503.14)
  region net SDC-TF-D1: 3961.74,3507.61 3955.74,3507.61 ccw(c3950.41,3507.61) 3953.22,3512.14 3964.25,3512.14 ccw(c3967.06,3507.61)
  region net VCC-READ: 4088.87,3571.27 4073.87,3571.27 ccw(c4004.88,3571.27) 4071.73,3588.34 4091.02,3588.34 ccw(c4157.87,3571.27)
  region net $1N1961: 4174.82,3620.51 4174.82,3614.51 ccw(c4174.82,3603.26) 4165.82,3610.01 4165.82,3625.01 ccw(c4174.82,3631.76)
  region net READ-VCC-EN: 4172.19,3725.05 4173.71,3712.42 ccw(c4195.79,3690.34) 4165.82,3699.1 4165.82,3724.1 ccw(c4168.37,3728.87)
  region net VBUS-USB: 4092.55,3736.08 4098.97,3721.29 ccw(c4130.79,3697.43) 4091.02,3697.43 4071.73,3725.08 ccw(c4064.32,3764.3)
  region net SEL1-LED: 4412.31,3581 4412.31,3591 ccw(c4412.31,3611.18) 4427.31,3597.68 4427.31,3573.5 ccw(c4412.31,3562.25)
  region net VBUS-USB: 4457.51,3567.16 4447.51,3567.16 ccw(c4428.86,3567.16) 4447,3571.5 4458.02,3571.5 ccw(c4476.16,3567.16)
  region net SEL-BTN: 4477.19,3563.84 4467.19,3563.84 ccw(c4409.64,3563.84) 4466.68,3571.5 4477.7,3571.5 ccw(c4534.74,3563.84)
  region net CPUX-RX: 4488.88,3717.5 4494.88,3717.5 ccw(c4512.26,3717.5) 4497.39,3708.5 4486.37,3708.5 ccw(c4471.5,3717.5)
  region net CPUX-TX: 4469.19,3717.5 4475.19,3717.5 ccw(c4492.57,3717.5) 4477.7,3708.5 4466.68,3708.5 ccw(c4451.81,3717.5)
  region net SEL: 4447.51,3710.84 4457.51,3710.84 ccw(c4463.11,3710.84) 4458.02,3708.5 4447,3708.5 ccw(c4441.91,3710.84)
  region net READ-VCC-EN: 4412.31,3690.41 4412.31,3700.41 ccw(c4412.31,3719.16) 4427.31,3707.91 4427.31,3682.91 ccw(c4412.31,3671.66)
  region net VDD-3V3: 3609.85,3197.99 3609.85,3217.99 3620.87,3218.23 3630.48,3219.87 3637.27,3224.32 3639.18,3228.04 3639.85,3232.99 3639.85,3183.76 3639.18,3188.67 3637.27,3192.31 3630.48,3196.5 3620.87,3197.88
  region net VDD-3V3: 3650.81,3262.07 3667.65,3257.7 3658.16,3250.52 3655.04,3246.93 3653.85,3241.2 3639.85,3241.2 3640.79,3246.96 3643.27,3252.49
  region net VCC-READ: 3676.85,3168.76 3666.85,3168.76 3664.85,3183.76 3678.85,3183.76
  region net LED-READ: 3726.85,3168.76 3716.85,3168.76 3714.85,3183.76 3728.85,3183.76
  region net VDD-3V3: 3751.85,3168.76 3741.85,3168.76 3739.85,3183.76 3753.85,3183.76
  region net USB0-DP: 3793.85,3248.5 3799.85,3248.5 3801.85,3243.86 3803.85,3241.2 3789.85,3241.2 3791.85,3243.86
  region net USB0-DM: 3819.73,3249.62 3831.56,3252.96 3828.84,3248.41 3828.55,3243.25 3814.85,3241.2 3816.37,3245.79
  region net SDC-READ-D2: 3668.85,3459.24 3674.85,3459.24 3676.85,3453.43 3678.85,3450.24 3664.85,3450.24 3666.85,3453.43
  region net SDC-READ-D3: 3693.85,3459.24 3699.85,3459.24 3701.85,3453.43 3703.85,3450.24 3689.85,3450.24 3691.85,3453.43
  region net SDC-READ-CMD: 3718.85,3459.24 3724.85,3459.24 3726.85,3453.43 3728.85,3450.24 3714.85,3450.24 3716.85,3453.43
  region net SDC-READ-CLK: 3743.85,3459.24 3749.85,3459.24 3751.85,3453.43 3753.85,3450.24 3739.85,3450.24 3741.85,3453.43
  region net SDC-READ-D0: 3768.85,3459.24 3774.85,3459.24 3776.85,3453.43 3778.85,3450.24 3764.85,3450.24 3766.85,3453.43
  region net SDC-READ-D1: 3793.85,3459.24 3799.85,3459.24 3801.85,3453.43 3803.85,3450.24 3789.85,3450.24 3791.85,3453.43
  region net VBUS-USB: 4419.31,3992.51 4434.31,3992.51 ccw(c4437.64,4013.52) 4437.64,3992.25 4415.98,3992.25 ccw(c4415.98,4013.52)
  region net CPUX-RX: 4404.25,3932.5 4394.25,3932.5 ccw(c4389.89,3932.5) 4393.34,3935.16 4405.16,3935.16 ccw(c4408.61,3932.5)
  region net CC1: 4382.56,3926.16 4376.56,3926.16 ccw(c4361.17,3926.16) 4373.65,3935.16 4385.47,3935.16 ccw(c4397.95,3926.16)
  region net USB0-DM: 4362.88,3929.66 4356.88,3929.66 ccw(c4350.22,3929.66) 4353.97,3935.16 4365.79,3935.16 ccw(c4369.54,3929.66)
  region net USB0-DM: 4323.51,3929.84 4317.51,3929.84 ccw(c4311.18,3929.84) 4314.6,3935.16 4326.42,3935.16 ccw(c4329.84,3929.84)
  region net USB0-DP: 4303.82,3926.16 4297.82,3926.16 ccw(c4282.43,3926.16) 4294.91,3935.16 4306.73,3935.16 ccw(c4319.21,3926.16)
  region net CPUX-TX: 4284.14,3927.79 4278.14,3927.79 ccw(c4267.34,3927.79) 4275.23,3935.16 4287.05,3935.16 ccw(c4294.94,3927.79)
  region net CPUX-TX: 4278.14,3995.79 4284.14,3995.79 ccw(c4287.75,3995.79) 4287.05,3992.25 4275.23,3992.25 ccw(c4274.53,3995.79)
  region net CC2: 4259.99,3929.8 4249.84,3928.14 ccw(c4218.93,3959.05) 4255.54,3935.16 4267.36,3935.16 ccw(c4280.73,3909.06)
  region net VBUS-USB: 4239.44,4007.69 4252.67,3999.72 ccw(c4284.49,3975.85) 4244.72,3975.85 4223.06,3992.25 ccw(c3966.71,4280.42)
  region net VCC-CARD: 3688.05,4099.09 3677.44,4109.7 3680.73,4112.81 3682.36,4116.67 3695.02,4104.01 3691.16,4102.38
  region net VCC-CARD: 3840.25,4166.7 3855.25,4166.11 3855.08,4161.61 3856.56,4157.71 3838.67,4158.3 3840.33,4162.15
  region net SEL1-LED: 4425.76,3591 4425.76,3581 4421.28,3579.77 4417.36,3577.05 4417.36,3594.95 4421.28,3592.23
  region net SEL1-LED: 4229.81,3522.46 4236.89,3529.54 4239.63,3528.54 4243.02,3528.99 4230.36,3516.33 4230.81,3519.72
  region net VCC-3V3-LDO: 4246.76,3429 4246.76,3419 4242.28,3417.77 4238.36,3415.05 4238.36,3432.95 4242.28,3430.23
  region net VCC-3V3-LDO: 4231.76,3762 4231.76,3742 4217.35,3739.99 4217.35,3764.01
  region net USB0-DM: 4337.35,3845.77 4343.35,3851.67 4345.48,3846.62 4350.15,3843.27 4334.01,3835.54
  region net USB0-DP: 4318.35,3851.74 4324.35,3847.77 4325.37,3831.31 4312.22,3843.33 4316.74,3846.21
  region net VCC-CARD: 4172.65,3264.63 4190.65,3264.19 4190.05,3259.79 4190.49,3255.78 4172.6,3256.22 4173.7,3260
  region net VCC-CARD: 3632.07,3702.12 3621.47,3712.72 3624.76,3715.84 3626.39,3719.69 3639.04,3707.04 3635.19,3705.41
  region net VCC-CARD: 3644.68,3735.93 3655.28,3725.33 3651.99,3722.21 3650.36,3718.36 3637.71,3731.01 3641.56,3732.64
  region net VCC-3V3-LDO: 3715.94,3712.51 3715.94,3722.51 3720.43,3723.74 3724.34,3726.46 3724.34,3708.56 3720.43,3711.28
  region net VCC-3V3-LDO: 3967.94,3712.51 3967.94,3722.51 3972.43,3723.74 3976.34,3726.46 3976.34,3708.56 3972.43,3711.28
  region net VCC-3V3-LDO: 3983.42,3697.51 3973.42,3703.17 3972.6,3715.05 3987.47,3705.91 3984.12,3702.73
  region net SEL: 3667,3684.14 3659.92,3677.06 3657.02,3678.25 3653.48,3678.02 3666.35,3690.46 3665.93,3686.98
  region net USB0-DM: 4389.35,3219.64 4383.35,3223.59 4382.34,3240.08 4395.48,3228.05 4390.95,3225.17
  region net USB0-DP: 4372.47,3233.12 4368.23,3228.88 4364.7,3228.99 4360.68,3228.01 4373.34,3240.67 4372.36,3236.65
  region net SEL: 4385.42,3715.14 4392.49,3708.07 4390.19,3704.02 4389.34,3699.33 4376.68,3711.99 4381.37,3712.84
  region net CPUX-RX: 4386.08,4003.52 4381.83,3999.27 4377.25,4001.23 4371.68,4001.01 4384.34,4013.67 4384.12,4008.11
  region net CPUX-RX: 4494.88,3764.03 4488.88,3769.12 4486.5,3782.08 4501.58,3772.43 4496.97,3769.18
  region net CPUX-TX: 4475.19,3764.75 4469.19,3760.66 4467.56,3766.15 4463.04,3769.06 4476.36,3780.86
  region net VBUS-USB: 4265.82,4025.91 4254.03,4035.33 4257.31,4038.57 4258.71,4042.54 4272.5,4031.13 4268.79,4029.25
  region net VBUS-USB: 4277.01,4059.91 4287.61,4049.3 4284.33,4046.19 4282.7,4042.33 4270.04,4054.99 4273.89,4056.62
  region net CPUX-TX: 4324.97,4013.49 4319.57,4019.49 4324.68,4021.6 4327.97,4026.24 4336.92,4010.74
  region net VCC-READ: 3676.85,3141.39 3666.85,3141.39 3665.62,3145.87 3662.9,3149.79 3680.8,3149.79 3678.08,3145.87
  region net VCC-READ: 3666.85,3174.21 3676.85,3174.21 3678.08,3169.72 3680.8,3165.8 3662.9,3165.8 3665.62,3169.72
  region net VCC-READ: 4092.44,3532.3 4103.05,3542.91 4106.16,3539.62 4110.02,3537.99 4097.36,3525.33 4095.73,3529.19
  region net SEL: 3668.46,3655.74 cw(c3724.54,3655.3) 3684.89,3694.95 3677.81,3702.03 cw(c3656.55,3723.29) 3657.89,3693.25 3650.81,3686.18 cw(c3594.05,3655.74) 3658.46,3655.74
  region net USB0-DM: 4354.34,3919.88 cw(c4353.25,3916.42) 4356.88,3916.42 4359.88,3929.66 4356.88,3936.9 cw(c4332.66,3941.56) 4350.1,3924.12
Bottom Layer:
  region net VCC-CARD: 3697.47,4133.26 3711.61,4119.12 3702.84,4107.51 3685.86,4124.49
  region net VCC-CARD: 3832.94,4140 3832.94,4160 3847.35,4162.01 3847.35,4137.99
  region net SEL1-LED: 4401.28,3570.86 4394.21,3577.93 4396.51,3581.98 4397.36,3586.67 4410.02,3574.01 4405.33,3573.16
  region net SEL1-LED: 4250.42,3532.14 4257.49,3525.07 4255.19,3521.02 4254.34,3516.33 4241.68,3528.99 4246.37,3529.84
  region net VCC-3V3-LDO: 4214.23,3734.74 4200.09,3748.88 4208.86,3760.49 4225.84,3743.51
  region net USB0-DM: 4344.35,3813.16 4338.35,3819.39 4336.73,3823.67 4334.36,3827.8 4351.13,3821.56 4346.47,3818.13
  region net USB0-DP: 4327.16,3822.43 4323.23,3817.88 4318.66,3819.76 4313.12,3819.37 4325.32,3832.48 4325.19,3826.97
  region net VCC-CARD: 4171.35,3262.41 4191.35,3262.41 4193.36,3248 4169.34,3248
  region net VCC-CARD: 3631.14,3701.64 3618.29,3717.08 3623.06,3718.59 3625.33,3719.18 3626.49,3720.76 3637.63,3707.04 3633.96,3705.46
  region net VCC-3V3-LDO: 3748.76,3722.51 3748.76,3712.51 3744.28,3711.28 3740.36,3708.56 3740.36,3726.46 3744.28,3723.74
  region net VCC-3V3-LDO: 3998.76,3727.51 3998.76,3707.51 3984.35,3705.5 3984.35,3729.52
  region net VCC-3V3-LDO: 3967.94,3712.51 3967.94,3722.51 3972.43,3723.74 3976.34,3726.46 3976.34,3708.56 3972.43,3711.28
  region net SEL: 3662.42,3705.14 3669.49,3698.07 3667.19,3694.02 3666.34,3689.33 3653.68,3701.99 3658.37,3702.84
  region net USB0-DM: 4382.23,3247.88 4386.47,3252.12 4390.5,3251.51 4395.02,3251.99 4382.36,3239.33 4382.84,3243.85
  region net USB0-DP: 4366.35,3260.36 4372.35,3256.41 4373.36,3239.92 4360.22,3251.95 4364.75,3254.83
  region net SEL: 4360.94,3695 4360.94,3705 4365.43,3706.23 4369.34,3708.95 4369.34,3691.05 4365.43,3693.77
  region net CPUX-RX: 4364.47,3999.88 4360.23,4004.12 4361.55,4006.19 4361.44,4008.06 4360.34,4012.96 4373.72,4001.07 4368.61,4001.49
  region net CPUX-RX: 4485.51,3797.6 4493.48,3798.11 4497.77,3796.33 4502.52,3795.26 4486.7,3786.89 4487.5,3792.63
  region net CPUX-TX: 4461.35,3795.14 4467.35,3795.14 4469.77,3791.86 4473.3,3789.01 4455.4,3789.01 4458.93,3791.86
  region net CPUX-TX: 4342.35,4006.06 4336.35,4006.1 4334.49,4010.73 4330.41,4014.51 4348.31,4014.47 4344.21,4010.69
  region net VCC-READ: 3688.26,3165.3 3688.26,3150.3 3683.73,3150.42 3679.86,3148.85 3679.86,3166.75 3683.73,3165.17
  region net VCC-READ: 4126.26,3519.7 4115.65,3509.09 4112.54,3512.38 4108.68,3514.01 4121.34,3526.67 4122.97,3522.81

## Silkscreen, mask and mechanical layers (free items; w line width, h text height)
Top Silkscreen Layer:
  region: 3956.63,3318 ccw(c3940.35,3318) 3924.07,3318 ccw(c3940.35,3318)
  lines w6: 4124.35,3474.64 4124.35,3457.49 ; 4140,3457.49 4124.35,3457.49 ; 4180.75,3474.85 4141.71,3474.85 4124.35,3457.49
  text "ON->BOARD /  OFF->CARD" at 3854.88,3353.1 h36.18
  text "SWITCH" at 4310.9,3333.32 h38.94
Bottom Silkscreen Layer:
  text "v1.1" at 4080.67,4151.03 h38.94 r90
